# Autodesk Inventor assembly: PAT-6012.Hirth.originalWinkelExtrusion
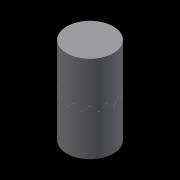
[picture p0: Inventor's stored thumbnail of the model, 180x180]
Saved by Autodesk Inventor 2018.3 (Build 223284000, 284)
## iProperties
Created: 2020-03
Part Number: PAT-6012.Hirth.originalWinkelExtrusion
Document SubType Name: Assembly
Designer: Th. Mörgeli
Mass: 35.2883 g
Surface Area: 96.7252 cm^2
Volume: 35.2883 cm^3
Density: 1 g/cm^3
Author: Th. Mörgeli
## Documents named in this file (2)
- C:\Users\mothomas\Documents\Inventor\Patterson\PATHirth.originalWinkelExtrusion.iam
- C:\Users\mothomas\Documents\Inventor\Patterson\PATHirth.originalWinkelExtrusion.ipt
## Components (2 placed, 1 different names)
1. PATHirth.originalWinkelExtrusion:1 — Mate:1, Mate:2, Angle:1
2. PATHirth.originalWinkelExtrusion:2 — Mate:1, Mate:2, Angle:1
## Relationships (3: Mate 2, Angle 1)
- Mate:1: PATHirth.originalWinkelExtrusion:1 ↔ PATHirth.originalWinkelExtrusion:2
- Mate:2: PATHirth.originalWinkelExtrusion:1 ↔ PATHirth.originalWinkelExtrusion:2
- Angle:1: PATHirth.originalWinkelExtrusion:1 ↔ PATHirth.originalWinkelExtrusion:2
